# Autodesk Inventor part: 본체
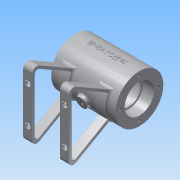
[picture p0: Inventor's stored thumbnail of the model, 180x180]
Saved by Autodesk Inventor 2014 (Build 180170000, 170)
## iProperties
Created: 2016-03
Part Number: 본체
Material: 알루미늄 6061
Document SubType Name: Modeling
Designer: SCD-A12
Density: 2.71 g/cm^3
Appearance: 알루미늄 - 평지
Author: SCD-A12
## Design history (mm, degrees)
sketch "스케치1"
  geometry: L1 (-35, 0)-(35, 0); L2 (-35, 16)-(-35, 26); L3 (-35, 26)-(35, 26); L4 (35, 26)-(35, 16); L5 (-35, 16)-(-23, 16); L6 (-23, 16)-(-23, 14); L7 (-23, 14)-(-21, 14); L8 (-21, 14)-(-21, 21); L9 (-21, 21)-(21, 21); L10 (21, 21)-(21, 14); L11 (21, 14)-(23, 14); L12 (23, 14)-(23, 16); L13 (23, 16)-(35, 16); 2 further points
  constraints: 26 end point, 7 perpendicular, 4 parallel, 1 coincident, 1 collinear, 1 horizontal, 1 midpoint
  dimensions: "d0" = 70 distance of L1.start L1.end; "d1" = 12 distance of L2.start L5.end; "d2" = 42 distance of L8.end L9.end; "d3" = 12 distance of L4.end L12.end; "d4" = 2 distance of L6.end L7.end; "d5" = 52 diameter of L3 L1; "d6" = 32 diameter of L5 L1; "d7" = 32 diameter of L13 L1; "d8" = 42 diameter of L9 L1; "d9" = 28 diameter of L7 L1; "d10" = 28 diameter of L11 L1
revolve "회전1" sketch "스케치1" stored, may be unused: angle "d11" = 90 deg
node "작업 평면1"
sketch "스케치2"
  geometry: C1 r 5 at (0, 0); 1 further point
  constraints: 1 centre point, 1 coincident
  dimensions: "d13" = 10 diameter of C1
extrude "돌출1" join sketch "스케치2" distance "d14" = 3; taper "d15" = 0 deg; dims "d16" = 1.5, "d17" = 0
sketch "스케치3"
  geometry: C1 r 5 at (0, 0) reference; 1 further point
  constraints: 1 coincident
hole "구멍1" sketch "스케치3" at (0, 0) diameter "d18" = 5.188; stored, may be unused: countersink angle "d22" = 90 deg, drill point angle "d24" = 118 deg; dims "d19" = 8, "d20" = 4, "d21" = 2, "d23" = 10
sketch "스케치4"
  geometry: 1 further point
hole "구멍2" sketch "스케치4" at (0, 21) diameter "d26" = 3.242; stored, may be unused: countersink angle "d30" = 90 deg, drill point angle "d32" = 118 deg; dims "d27" = 8, "d28" = 4, "d29" = 2, "d31" = 10
node "작업 평면6"
sketch "스케치9"
  geometry: L1 (-35, -26)-(-35, 26) reference; L2 (-35, 26)-(35, 26) reference; 2 further points
  constraints: 1 other
  dimensions: "d61" = 35 distance from line of L1 point (0, 0); "d62" = 26 distance from line of L2 point (0, 0)
feature "엠보싱1" sketch "스케치9" dims "d0" = 70, "d1" = 12, "d2" = 42, "d3" = 12, "d4" = 2, "d5" = 52, "d6" = 32, "d7" = 32, "d8" = 42, "d9" = 28, "d10" = 28, "d63" = 0.5, "d64" = 0
node "작업 평면8"
sketch "스케치10"
  geometry: C1 r 6 at (0, 0); 1 further point
  constraints: 1 centre point, 1 coincident
  dimensions: "d67" = 12 diameter of C1
extrude "돌출3" join sketch "스케치10" distance "d68" = 3; taper "d70" = 0 deg; dims "d69" = 1.5, "d71" = 0
sketch "스케치11"
  geometry: C1 r 6 at (0, 0) reference; 1 further point
  constraints: 1 coincident
hole "구멍5" sketch "스케치11" at (0, 0) diameter "d72" = 5.188; stored, may be unused: countersink angle "d76" = 90 deg, drill point angle "d78" = 118 deg; dims "d73" = 8, "d74" = 4, "d75" = 2, "d77" = 12
node "작업 평면14"
sketch "스케치17"
  geometry: L1 (-22.517, -13)-(-65, -37.528); L2 (0, 0)-(79.269, 0); L3 (-65, 0)-(-65, -37.528); L4 (-22.517, 13)-(-65, 37.528); L5 (-65, 0)-(-65, 37.528); A1 r 26 centre (0, 0) between (-22.517, 13) and (-22.517, -13); 1 further point
  constraints: 10 end point, 2 point on circle, 1 centre point, 1 horizontal, 1 perpendicular
  dimensions: "d110" = 65 distance of L2.start L3.start; "d111" = 150 deg angle of L1 L2
feature "리브1" sketch "스케치17" dims "d112" = 3, "d113" = 10, "d114" = 0, "d115" = 0, "d116" = 1, "d117" = 1
fillet "모깎기1" dims "d118" = 5
fillet "모깎기2" dims "d119" = 3
fillet "모깎기3" dims "d120" = 0.3
fillet "모깎기4" dims "d121" = 2
fillet "모깎기5" dims "d122" = 3
sketch "스케치18"
  geometry: L1 (0, 0)-(0, 59.467) reference; C1 r 3 at (5, 9.734); 1 further point
  constraints: 1 centre point
  dimensions: "d123" = 6 diameter of C1; "d124" = 20 horizontal distance of point (-15, 29.734) C1.centre; "d125" = 5 distance from line of L1 C1.centre
extrude "돌출6" cut sketch "스케치18" stored distance "d126" = 0; taper "d127" = 0 deg
fillet "모깎기6" dims "d134" = 3
fillet "모깎기7" dims "d135" = 0.5
node "솔리드1"
pattern_circular "원형 패턴1" dims angle "d34" = 360 deg
mirror "대칭1"
mirror "대칭3"
pattern_linear "직사각형 패턴1" dims "d130" = 40
other parameters: "d12" = 26, "d60" = 29.5, "d109" = 25
